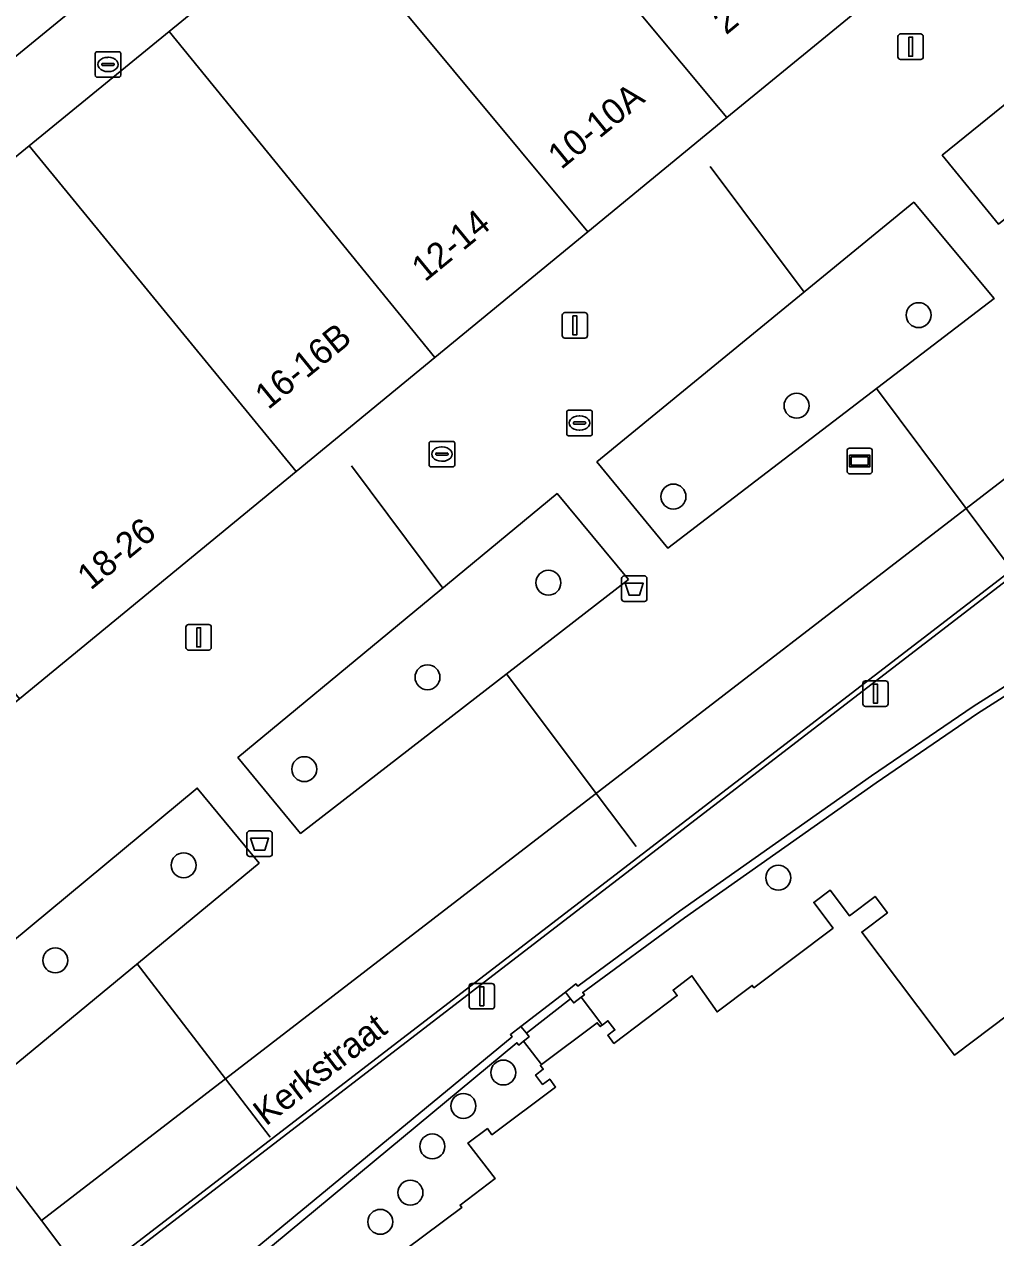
# Model space of a CAD drawing. Extents: x 161087 to 161926, y 382572 to 383873.
# Drawn here: x 161362.19 to 161400.27, y 383099.2 to 383146.78 of the extents above; entities that cross this region are included whole.
import ezdxf

# ---------------------------------------------------------------- set-up
doc = ezdxf.new("R2010")
doc.units = 0
for name, color, linetype in [('IMGEO_Afvalbak', 7, 'Continuous'), ('IMGEO_Boom', 7, 'Continuous'), ('IMGEO_Brandkraan', 7, 'Continuous'), ('IMGEO_Erf', 7, 'Continuous'), ('IMGEO_Groenvoorziening', 7, 'Continuous'), ('IMGEO_Haag', 7, 'Continuous'), ('IMGEO_Kolk', 7, 'Continuous'), ('IMGEO_Lichtmast', 7, 'Continuous'), ('IMGEO_Lijnafwatering', 7, 'Continuous'), ('IMGEO_Muur', 7, 'Continuous'), ('IMGEO_Openbare_ruimte_label', 7, 'Continuous'), ('IMGEO_Pand', 7, 'Continuous'), ('IMGEO_Pand_nummerreeks', 7, 'Continuous'), ('IMGEO_Reclamebord', 7, 'Continuous'), ('IMGEO_Rijbaan_lokaal_open', 7, 'Continuous'), ('IMGEO_Rioolput', 7, 'Continuous'), ('IMGEO_Voetgangersgebied_open', 7, 'Continuous'), ('IMGEO_Voetpad_op_trap', 7, 'Continuous'), ('IMGEO_Voetpad_open', 7, 'Continuous')]:
    doc.layers.add(name, color=color, linetype=linetype)

msp = doc.modelspace()

# ---------------------------------------------------------------- linework, layer by layer
at = {"layer": 'IMGEO_Afvalbak'}
for p, q in [((161385.607, 383124.25), (161385.607, 383125.05)), ((161385.607, 383125.05), (161385.607, 383124.25)), ((161385.707, 383125.15), (161386.497, 383125.15)), ((161386.497, 383125.15), (161385.707, 383125.15)), ((161386.597, 383125.05), (161386.597, 383124.25)), ((161386.597, 383124.25), (161386.597, 383125.05)), ((161386.497, 383124.15), (161385.707, 383124.15)), ((161385.707, 383124.15), (161386.497, 383124.15)), ((161370.919, 383114.252), (161370.919, 383115.052)), ((161370.919, 383115.052), (161370.919, 383114.252)), ((161371.019, 383115.152), (161371.809, 383115.152)), ((161371.809, 383115.152), (161371.019, 383115.152)), ((161371.909, 383115.052), (161371.909, 383114.252)), ((161371.909, 383114.252), (161371.909, 383115.052)), ((161371.809, 383114.152), (161371.019, 383114.152)), ((161371.019, 383114.152), (161371.809, 383114.152))]:
    msp.add_line(p, q, dxfattribs=at)
for points in [[(161385.75, 383124.864), (161386.454, 383124.864), (161386.305, 383124.394), (161385.899, 383124.394), (161385.75, 383124.864)], [(161371.062, 383114.866), (161371.766, 383114.866), (161371.617, 383114.396), (161371.211, 383114.396), (161371.062, 383114.866)]]:
    msp.add_lwpolyline(points, dxfattribs=at)
for centre, start, end in [((161385.707, 383125.05), 90, 180), ((161385.707, 383125.05), 90, 180), ((161386.497, 383125.05), 0, 90), ((161386.497, 383125.05), 360, 90), ((161385.707, 383124.25), 180, 270), ((161385.707, 383124.25), 180, 270), ((161386.497, 383124.25), 270, 0), ((161386.497, 383124.25), 270, 0), ((161371.019, 383115.052), 90, 180), ((161371.019, 383115.052), 90, 180), ((161371.809, 383115.052), 0, 90), ((161371.809, 383115.052), 360, 90), ((161371.019, 383114.252), 180, 270), ((161371.019, 383114.252), 180, 270), ((161371.809, 383114.252), 270, 0), ((161371.809, 383114.252), 270, 0)]:
    msp.add_arc(centre, 0.1, start, end, dxfattribs=at)
at = {"layer": 'IMGEO_Boom'}
for centre in [(161397.247, 383135.375), (161392.462, 383131.824), (161387.637, 383128.263), (161382.735, 383124.885), (161377.996, 383121.178), (161373.166, 383117.575), (161368.435, 383113.807), (161391.746, 383113.319), (161363.406, 383110.079), (161380.968, 383105.681), (161379.403, 383104.373), (161378.185, 383102.786), (161377.328, 383100.971), (161376.145, 383099.827)]:
    msp.add_circle(centre, 0.489, dxfattribs=at)
at = {"layer": 'IMGEO_Brandkraan'}
for p, q in [((161383.454, 383130.721), (161383.454, 383131.573)), ((161383.529, 383131.647), (161384.381, 383131.647)), ((161384.455, 383131.573), (161384.455, 383130.721)), ((161383.713, 383131.141), (161383.713, 383131.153)), ((161384.151, 383131.104), (161383.753, 383131.104)), ((161383.756, 383131.19), (161384.154, 383131.19)), ((161383.942, 383131.427), (161383.967, 383131.427)), ((161384.197, 383131.153), (161384.197, 383131.141)), ((161384.381, 383130.647), (161383.529, 383130.647)), ((161383.965, 383130.867), (161383.94, 383130.867))]:
    msp.add_line(p, q, dxfattribs=at)
for points in [[(161383.454, 383130.721), (161383.454, 383131.573)], [(161383.529, 383131.647), (161384.381, 383131.647)], [(161384.455, 383131.573), (161384.455, 383130.721)], [(161384.381, 383130.647), (161383.529, 383130.647)]]:
    msp.add_lwpolyline(points, dxfattribs=at)
for centre, radius, start, end in [((161383.531, 383131.571), 0.0765, 91.552, 178.448), ((161383.531, 383131.571), 0.0765, 91.552, 178.448), ((161384.379, 383131.571), 0.0765, 1.552, 88.448), ((161384.379, 383131.571), 0.0765, 1.552, 88.448), ((161383.753, 383131.15), 0.0403, 85.8775, 175.7526), ((161383.75, 383131.14), 0.0366, 178.938, 274.7102), ((161384.154, 383131.147), 0.043, 264.8664, 352.4533), ((161384.158, 383131.152), 0.0386, 1.7309, 96.639), ((161383.531, 383130.723), 0.0765, 181.552, 268.448), ((161383.531, 383130.723), 0.0765, 181.552, 268.448), ((161384.379, 383130.723), 0.0765, 271.552, 358.448), ((161384.379, 383130.723), 0.0765, 271.552, 358.448)]:
    msp.add_arc(centre, radius, start, end, dxfattribs=at)
for centre, major_axis, ratio, start_param, end_param in [((161383.941, 383131.147), (-0.387, 0.002), 0.722429, 4.712389, 7.853982), ((161383.966, 383131.147), (-0.39, 0.002), 0.717154, 1.570796, 4.712389)]:
    msp.add_ellipse(centre, major_axis=major_axis, ratio=ratio, start_param=start_param, end_param=end_param, dxfattribs=at)
at = {"layer": 'IMGEO_Erf'}
for points in [[(161404.509, 383122.902), (161399.561, 383119.758), (161395.582, 383117.045), (161388.067, 383111.744), (161384.079, 383108.819), (161384.146, 383108.732), (161384.022, 383108.636), (161384.745, 383107.674), (161384.844, 383107.54), (161385.071, 383107.711), (161385.342, 383107.352), (161385.063, 383107.141), (161385.304, 383106.822), (161387.786, 383108.696), (161387.622, 383108.913), (161388.358, 383109.473), (161389.349, 383108.059), (161390.723, 383109.094), (161390.789, 383109.006), (161393.896, 383111.347), (161393.138, 383112.353), (161393.777, 383112.835), (161394.535, 383111.828), (161395.542, 383112.586), (161396.023, 383111.947), (161395.016, 383111.189), (161398.651, 383106.365), (161402.916, 383109.578)], [(161376.365, 383098.164), (161379.342, 383100.395), (161379.273, 383100.486), (161380.648, 383101.52), (161379.581, 383102.912), (161380.342, 383103.481), (161380.522, 383103.241), (161383.019, 383105.111), (161382.785, 383105.424), (161382.505, 383105.214), (161382.23, 383105.582), (161382.534, 383105.81), (161382.42, 383105.962), (161382.467, 383105.997), (161381.761, 383106.908), (161381.572, 383106.759), (161381.504, 383106.846), (161368.628, 383096.166)]]:
    msp.add_lwpolyline(points, dxfattribs=at)
at = {"layer": 'IMGEO_Groenvoorziening'}
for points in [[(161400.206, 383136.021), (161397.058, 383139.799), (161384.635, 383129.62), (161387.42, 383126.235)], [(161385.878, 383125.009), (161383.075, 383128.38), (161370.565, 383118.026), (161373.018, 383115.058)], [(161355.325, 383105.517), (161357.76, 383102.637), (161359.598, 383104.154), (161371.397, 383113.893), (161368.972, 383116.831), (161357.325, 383107.176)]]:
    msp.add_lwpolyline(points, close=True, dxfattribs=at)
at = {"layer": 'IMGEO_Haag'}
for points in [[(161400.206, 383136.021), (161397.058, 383139.799), (161384.635, 383129.62), (161387.42, 383126.235)], [(161385.878, 383125.009), (161383.075, 383128.38), (161370.565, 383118.026), (161373.018, 383115.058)], [(161355.325, 383105.517), (161357.76, 383102.637), (161359.598, 383104.154), (161371.397, 383113.893), (161368.972, 383116.831), (161357.325, 383107.176)]]:
    msp.add_lwpolyline(points, close=True, dxfattribs=at)
at = {"layer": 'IMGEO_Kolk'}
for p, q in [((161364.972, 383144.777), (161364.972, 383145.629)), ((161365.047, 383145.703), (161365.899, 383145.703)), ((161365.46, 383145.483), (161365.485, 383145.483)), ((161365.973, 383145.629), (161365.973, 383144.777)), ((161365.231, 383145.197), (161365.231, 383145.209)), ((161365.669, 383145.16), (161365.271, 383145.16)), ((161365.274, 383145.246), (161365.672, 383145.246)), ((161365.483, 383144.923), (161365.458, 383144.923)), ((161365.715, 383145.209), (161365.715, 383145.197)), ((161365.899, 383144.703), (161365.047, 383144.703))]:
    msp.add_line(p, q, dxfattribs=at)
for points in [[(161364.972, 383144.777), (161364.972, 383145.629)], [(161365.047, 383145.703), (161365.899, 383145.703)], [(161365.973, 383145.629), (161365.973, 383144.777)], [(161365.899, 383144.703), (161365.047, 383144.703)]]:
    msp.add_lwpolyline(points, dxfattribs=at)
for centre, radius, start, end in [((161365.049, 383145.627), 0.0765, 91.552, 178.448), ((161365.049, 383145.627), 0.0765, 91.552, 178.448), ((161365.897, 383145.627), 0.0765, 1.552, 88.448), ((161365.897, 383145.627), 0.0765, 1.552, 88.448), ((161365.271, 383145.206), 0.0403, 85.8775, 175.7526), ((161365.268, 383145.196), 0.0366, 178.938, 274.7102), ((161365.672, 383145.203), 0.043, 264.8664, 352.4533), ((161365.676, 383145.208), 0.0386, 1.7309, 96.639), ((161365.049, 383144.779), 0.0765, 181.552, 268.448), ((161365.049, 383144.779), 0.0765, 181.552, 268.448), ((161365.897, 383144.779), 0.0765, 271.552, 358.448), ((161365.897, 383144.779), 0.0765, 271.552, 358.448)]:
    msp.add_arc(centre, radius, start, end, dxfattribs=at)
for centre, major_axis, ratio, start_param, end_param in [((161365.459, 383145.203), (-0.387, 0.002), 0.722429, 4.712389, 7.853982), ((161365.484, 383145.203), (-0.39, 0.002), 0.717154, 1.570796, 4.712389)]:
    msp.add_ellipse(centre, major_axis=major_axis, ratio=ratio, start_param=start_param, end_param=end_param, dxfattribs=at)
at = {"layer": 'IMGEO_Lichtmast'}
for p, q in [((161396.438, 383145.499), (161396.438, 383146.299)), ((161396.438, 383146.299), (161396.438, 383145.499)), ((161396.538, 383146.399), (161397.328, 383146.399)), ((161397.328, 383146.399), (161396.538, 383146.399)), ((161397.428, 383146.299), (161397.428, 383145.499)), ((161397.428, 383145.499), (161397.428, 383146.299)), ((161397.328, 383145.399), (161396.538, 383145.399)), ((161396.538, 383145.399), (161397.328, 383145.399)), ((161383.279, 383134.575), (161383.279, 383135.375)), ((161383.279, 383135.375), (161383.279, 383134.575)), ((161383.379, 383135.475), (161384.169, 383135.475)), ((161384.169, 383135.475), (161383.379, 383135.475)), ((161384.269, 383135.375), (161384.269, 383134.575)), ((161384.269, 383134.575), (161384.269, 383135.375)), ((161384.169, 383134.475), (161383.379, 383134.475)), ((161383.379, 383134.475), (161384.169, 383134.475)), ((161368.528, 383122.344), (161368.528, 383123.144)), ((161368.528, 383123.144), (161368.528, 383122.344)), ((161368.628, 383123.244), (161369.418, 383123.244)), ((161369.418, 383123.244), (161368.628, 383123.244)), ((161369.518, 383123.144), (161369.518, 383122.344)), ((161369.518, 383122.344), (161369.518, 383123.144)), ((161369.418, 383122.244), (161368.628, 383122.244)), ((161368.628, 383122.244), (161369.418, 383122.244)), ((161395.161, 383121.035), (161395.951, 383121.035)), ((161395.951, 383121.035), (161395.161, 383121.035)), ((161395.061, 383120.135), (161395.061, 383120.935)), ((161395.061, 383120.935), (161395.061, 383120.135)), ((161396.051, 383120.935), (161396.051, 383120.135)), ((161396.051, 383120.135), (161396.051, 383120.935)), ((161395.951, 383120.035), (161395.161, 383120.035)), ((161395.161, 383120.035), (161395.951, 383120.035)), ((161379.732, 383109.172), (161380.522, 383109.172)), ((161380.522, 383109.172), (161379.732, 383109.172)), ((161379.632, 383108.272), (161379.632, 383109.072)), ((161379.632, 383109.072), (161379.632, 383108.272)), ((161380.622, 383109.072), (161380.622, 383108.272)), ((161380.622, 383108.272), (161380.622, 383109.072)), ((161380.522, 383108.172), (161379.732, 383108.172)), ((161379.732, 383108.172), (161380.522, 383108.172))]:
    msp.add_line(p, q, dxfattribs=at)
for points in [[(161396.858, 383146.274), (161397.008, 383146.274), (161397.008, 383145.524), (161396.858, 383145.524), (161396.858, 383146.274)], [(161383.699, 383135.35), (161383.849, 383135.35), (161383.849, 383134.6), (161383.699, 383134.6), (161383.699, 383135.35)], [(161368.948, 383123.119), (161369.098, 383123.119), (161369.098, 383122.369), (161368.948, 383122.369), (161368.948, 383123.119)], [(161395.481, 383120.91), (161395.631, 383120.91), (161395.631, 383120.16), (161395.481, 383120.16), (161395.481, 383120.91)], [(161380.052, 383109.047), (161380.202, 383109.047), (161380.202, 383108.297), (161380.052, 383108.297), (161380.052, 383109.047)]]:
    msp.add_lwpolyline(points, dxfattribs=at)
for centre, start, end in [((161396.538, 383146.299), 90, 180), ((161396.538, 383146.299), 90, 180), ((161397.328, 383146.299), 0, 90), ((161397.328, 383146.299), 360, 90), ((161396.538, 383145.499), 180, 270), ((161396.538, 383145.499), 180, 270), ((161397.328, 383145.499), 270, 0), ((161397.328, 383145.499), 270, 0), ((161383.379, 383135.375), 90, 180), ((161383.379, 383135.375), 90, 180), ((161384.169, 383135.375), 0, 90), ((161384.169, 383135.375), 360, 90), ((161383.379, 383134.575), 180, 270), ((161383.379, 383134.575), 180, 270), ((161384.169, 383134.575), 270, 0), ((161384.169, 383134.575), 270, 0), ((161368.628, 383123.144), 90, 180), ((161368.628, 383123.144), 90, 180), ((161369.418, 383123.144), 0, 90), ((161369.418, 383123.144), 360, 90), ((161368.628, 383122.344), 180, 270), ((161368.628, 383122.344), 180, 270), ((161369.418, 383122.344), 270, 0), ((161369.418, 383122.344), 270, 0), ((161395.161, 383120.935), 90, 180), ((161395.161, 383120.935), 90, 180), ((161395.951, 383120.935), 0, 90), ((161395.951, 383120.935), 360, 90), ((161395.161, 383120.135), 180, 270), ((161395.161, 383120.135), 180, 270), ((161395.951, 383120.135), 270, 0), ((161395.951, 383120.135), 270, 0), ((161379.732, 383109.072), 90, 180), ((161379.732, 383109.072), 90, 180), ((161380.522, 383109.072), 0, 90), ((161380.522, 383109.072), 360, 90), ((161379.732, 383108.272), 180, 270), ((161379.732, 383108.272), 180, 270), ((161380.522, 383108.272), 270, 0), ((161380.522, 383108.272), 270, 0)]:
    msp.add_arc(centre, 0.1, start, end, dxfattribs=at)
at = {"layer": 'IMGEO_Lijnafwatering'}
for points in [[(161392.763, 383136.28), (161389.082, 383141.199)], [(161400.84, 383125.485), (161399.111, 383127.795), (161395.596, 383132.493)], [(161378.599, 383124.675), (161375.014, 383129.473)], [(161386.413, 383114.242), (161400.925, 383125.4)], [(161386.169, 383114.545), (161384.609, 383116.624), (161381.095, 383121.307)], [(161371.911, 383103.092), (161386.413, 383114.242)], [(161371.832, 383103.147), (161370.078, 383105.431), (161366.613, 383109.945)], [(161364.65, 383097.51), (161371.911, 383103.092)]]:
    msp.add_lwpolyline(points, dxfattribs=at)
at = {"layer": 'IMGEO_Muur'}
msp.add_lwpolyline([(161404.347, 383123.179), (161399.385, 383120.025), (161395.4, 383117.308), (161387.88, 383112.004), (161383.887, 383109.068), (161383.816, 383109.153), (161383.403, 383108.826), (161383.604, 383108.566), (161383.727, 383108.407), (161384.022, 383108.636), (161384.146, 383108.732), (161384.079, 383108.819), (161388.067, 383111.744), (161395.582, 383117.045), (161399.561, 383119.758), (161404.509, 383122.902)], dxfattribs=at)
msp.add_lwpolyline([(161381.504, 383106.846), (161381.572, 383106.759), (161381.761, 383106.908), (161381.981, 383107.081), (161381.872, 383107.22), (161381.659, 383107.49), (161381.249, 383107.167), (161381.312, 383107.086), (161368.405, 383096.423), (161368.328, 383096.515), (161367.896, 383096.148), (161368.174, 383095.82), (161368.265, 383095.714), (161368.402, 383095.83), (161368.507, 383095.919), (161368.699, 383096.083), (161368.628, 383096.166)], close=True, dxfattribs=at)
at = {"layer": 'IMGEO_Pand'}
for points in [[(161392.446, 383178.663), (161380.349, 383167.931), (161366.415, 383156.428), (161358.027, 383149.381), (161352.139, 383144.565), (161355.558, 383140.385), (161382.954, 383162.789), (161396.597, 383174.217)], [(161379.196, 383155.764), (161389.735, 383143.119), (161395.526, 383147.877), (161394.505, 383149.117), (161388.426, 383156.163), (161384.889, 383160.421)], [(161379.196, 383155.764), (161373.745, 383151.306), (161384.281, 383138.638), (161389.735, 383143.119)], [(161367.869, 383146.5), (161378.284, 383133.71), (161384.281, 383138.638), (161373.745, 383151.306)], [(161367.869, 383146.5), (161362.382, 383142.013), (161372.85, 383129.246), (161378.284, 383133.71)], [(161400.835, 383143.809), (161398.177, 383141.643), (161400.377, 383138.943), (161403.261, 383141.284), (161401.056, 383143.989)], [(161362.382, 383142.013), (161351.5, 383133.112), (161361.997, 383120.329), (161372.85, 383129.246)]]:
    msp.add_lwpolyline(points, close=True, dxfattribs=at)
msp.add_lwpolyline([(161402.916, 383109.578), (161398.651, 383106.365), (161395.016, 383111.189), (161396.023, 383111.947), (161395.542, 383112.586), (161394.535, 383111.828), (161393.777, 383112.835), (161393.138, 383112.353), (161393.896, 383111.347), (161390.789, 383109.006), (161390.723, 383109.094), (161389.349, 383108.059), (161388.358, 383109.473), (161387.622, 383108.913), (161387.786, 383108.696), (161385.304, 383106.822), (161385.063, 383107.141), (161385.342, 383107.352), (161385.071, 383107.711), (161384.844, 383107.54), (161384.768, 383107.482), (161384.653, 383107.634), (161382.467, 383105.997), (161382.42, 383105.962), (161382.534, 383105.81), (161382.23, 383105.582), (161382.505, 383105.214), (161382.785, 383105.424), (161383.019, 383105.111), (161380.522, 383103.241), (161380.342, 383103.481), (161379.581, 383102.912), (161380.648, 383101.52), (161379.273, 383100.486), (161379.342, 383100.395), (161376.365, 383098.164)], dxfattribs=at)
at = {"layer": 'IMGEO_Reclamebord'}
for p, q in [((161394.441, 383129.258), (161394.441, 383130.058)), ((161394.441, 383130.058), (161394.441, 383129.258)), ((161394.541, 383130.158), (161395.331, 383130.158)), ((161395.331, 383130.158), (161394.541, 383130.158)), ((161395.431, 383130.058), (161395.431, 383129.258)), ((161395.431, 383129.258), (161395.431, 383130.058)), ((161395.331, 383129.158), (161394.541, 383129.158)), ((161394.541, 383129.158), (161395.331, 383129.158))]:
    msp.add_line(p, q, dxfattribs=at)
for points in [[(161394.542, 383129.89), (161395.33, 383129.89), (161395.33, 383129.426), (161394.542, 383129.426), (161394.542, 383129.89)], [(161394.607, 383129.825), (161394.607, 383129.491), (161395.265, 383129.491), (161395.265, 383129.825), (161394.607, 383129.825)]]:
    msp.add_lwpolyline(points, dxfattribs=at)
for centre, start, end in [((161394.541, 383130.058), 90, 180), ((161394.541, 383130.058), 90, 180), ((161395.331, 383130.058), 0, 90), ((161395.331, 383130.058), 360, 90), ((161394.541, 383129.258), 180, 270), ((161394.541, 383129.258), 180, 270), ((161395.331, 383129.258), 270, 0), ((161395.331, 383129.258), 270, 0)]:
    msp.add_arc(centre, 0.1, start, end, dxfattribs=at)
at = {"layer": 'IMGEO_Rijbaan_lokaal_open'}
for points in [[(161331.884, 383123.579), (161334.699, 383120.333), (161336.976, 383117.545), (161337.445, 383117.924), (161341.44, 383121.151), (161342.01, 383121.612), (161340.173, 383123.848), (161345.91, 383128.541), (161351.5, 383133.112), (161362.382, 383142.013), (161367.869, 383146.5), (161373.745, 383151.306), (161379.196, 383155.764), (161384.889, 383160.421), (161382.954, 383162.789), (161355.558, 383140.385), (161351.874, 383137.347), (161347.38, 383133.706), (161343.527, 383130.482)], [(161362.829, 383095.814), (161364.77, 383097.35), (161362.866, 383099.876), (161359.598, 383104.154), (161357.76, 383102.637), (161353.934, 383096.833), (161331.379, 383078.376), (161324.754, 383073.591), (161319.89, 383069.645), (161317.769, 383067.924), (161324.746, 383059.32), (161325.561, 383058.315)]]:
    msp.add_lwpolyline(points, dxfattribs=at)
at = {"layer": 'IMGEO_Rioolput'}
for p, q in [((161378.06, 383129.501), (161378.06, 383130.353)), ((161378.135, 383130.427), (161378.987, 383130.427)), ((161378.548, 383130.207), (161378.573, 383130.207)), ((161379.061, 383130.353), (161379.061, 383129.501)), ((161378.319, 383129.921), (161378.319, 383129.933)), ((161378.757, 383129.884), (161378.359, 383129.884)), ((161378.362, 383129.97), (161378.76, 383129.97)), ((161378.571, 383129.647), (161378.546, 383129.647)), ((161378.803, 383129.933), (161378.803, 383129.921)), ((161378.987, 383129.427), (161378.135, 383129.427))]:
    msp.add_line(p, q, dxfattribs=at)
for points in [[(161378.06, 383129.501), (161378.06, 383130.353)], [(161378.135, 383130.427), (161378.987, 383130.427)], [(161379.061, 383130.353), (161379.061, 383129.501)], [(161378.987, 383129.427), (161378.135, 383129.427)]]:
    msp.add_lwpolyline(points, dxfattribs=at)
for centre, radius, start, end in [((161378.137, 383130.351), 0.0765, 91.552, 178.448), ((161378.137, 383130.351), 0.0765, 91.552, 178.448), ((161378.985, 383130.351), 0.0765, 1.552, 88.448), ((161378.985, 383130.351), 0.0765, 1.552, 88.448), ((161378.359, 383129.93), 0.0403, 85.8775, 175.7526), ((161378.356, 383129.92), 0.0366, 178.938, 274.7102), ((161378.76, 383129.927), 0.043, 264.8664, 352.4533), ((161378.764, 383129.932), 0.0386, 1.7309, 96.639), ((161378.137, 383129.503), 0.0765, 181.552, 268.448), ((161378.137, 383129.503), 0.0765, 181.552, 268.448), ((161378.985, 383129.503), 0.0765, 271.552, 358.448), ((161378.985, 383129.503), 0.0765, 271.552, 358.448)]:
    msp.add_arc(centre, radius, start, end, dxfattribs=at)
for centre, major_axis, ratio, start_param, end_param in [((161378.547, 383129.927), (-0.387, 0.002), 0.722429, 4.712389, 7.853982), ((161378.572, 383129.927), (-0.39, 0.002), 0.717154, 1.570796, 4.712389)]:
    msp.add_ellipse(centre, major_axis=major_axis, ratio=ratio, start_param=start_param, end_param=end_param, dxfattribs=at)
at = {"layer": 'IMGEO_Voetgangersgebied_open'}
for points in [[(161407.863, 383160.065), (161395.023, 383149.541), (161394.505, 383149.117), (161395.526, 383147.877), (161389.735, 383143.119), (161384.281, 383138.638), (161378.284, 383133.71), (161372.85, 383129.246), (161361.997, 383120.329), (161356.619, 383115.911), (161353.296, 383113.18), (161353.567, 383112.777), (161357.325, 383107.176), (161368.972, 383116.831), (161371.397, 383113.893), (161359.598, 383104.154), (161362.866, 383099.876), (161421.439, 383144.995)], [(161433.223, 383150.013), (161429.726, 383154.156), (161427.344, 383151.101), (161424.646, 383147.465), (161421.439, 383144.995), (161362.866, 383099.876), (161364.77, 383097.35), (161409.678, 383131.89)]]:
    msp.add_lwpolyline(points, dxfattribs=at)
for points in [[(161398.177, 383141.643), (161400.835, 383143.809), (161401.056, 383143.989), (161403.596, 383146.055), (161405.797, 383143.342), (161403.261, 383141.284), (161400.377, 383138.943)], [(161397.058, 383139.799), (161400.206, 383136.021), (161387.42, 383126.235), (161384.635, 383129.62)], [(161404.347, 383123.179), (161413.367, 383127.97), (161413.315, 383128.067), (161413.877, 383128.367), (161411.138, 383131.841), (161410.626, 383132.608), (161409.678, 383131.89), (161364.77, 383097.35), (161366.565, 383095.02), (161366.762, 383095.189), (161367.896, 383096.148), (161368.328, 383096.515), (161368.405, 383096.423), (161381.312, 383107.086), (161381.249, 383107.167), (161381.659, 383107.49), (161383.403, 383108.826), (161383.816, 383109.153), (161383.887, 383109.068), (161387.88, 383112.004), (161395.4, 383117.308), (161399.385, 383120.025)], [(161385.878, 383125.009), (161373.018, 383115.058), (161370.565, 383118.026), (161383.075, 383128.38)]]:
    msp.add_lwpolyline(points, close=True, dxfattribs=at)
at = {"layer": 'IMGEO_Voetpad_op_trap'}
msp.add_lwpolyline([(161384.653, 383107.634), (161384.768, 383107.482), (161384.844, 383107.54), (161384.745, 383107.674), (161384.022, 383108.636), (161383.727, 383108.407), (161383.604, 383108.566), (161381.872, 383107.22), (161381.981, 383107.081), (161381.761, 383106.908), (161382.467, 383105.997)], close=True, dxfattribs=at)
at = {"layer": 'IMGEO_Voetpad_open'}
msp.add_lwpolyline([(161383.604, 383108.566), (161383.403, 383108.826), (161381.659, 383107.49), (161381.872, 383107.22)], close=True, dxfattribs=at)

# ---------------------------------------------------------------- texts
at = {"layer": 'IMGEO_Openbare_ruimte_label'}
msp.add_text('Kerkstraat', height=1, rotation=37.5686, dxfattribs=at).set_placement((161371.661, 383103.559))
at = {"layer": 'IMGEO_Pand_nummerreeks'}
for s, rotation, p in [('2-8A', 39.4451, (161389.699, 383146.336)), ('10-10A', 39.1636, (161383.236, 383141.058)), ('12-14', 39.3304, (161377.895, 383136.652)), ('16-16B', 39.1126, (161371.749, 383131.644)), ('18-26', 39.408, (161364.79, 383124.564))]:
    msp.add_text(s, height=1, rotation=rotation, dxfattribs=at).set_placement(p)

doc.saveas('drawing.dxf')
